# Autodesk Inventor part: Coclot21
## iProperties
Created: 2011-05
Part Number: Coclot21
Document SubType Name: Modeling
Designer: 904Chiaki
Density: 1 g/cm^3
Mass: 303.621 g
Surface Area: 728.501 cm^2
Volume: 303.621 cm^3
Author: 904Chiaki
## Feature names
1. Revolution1
2. Chamfer1
3. Chamfer2
4. Chamfer4
5. Chamfer5
6. Chamfer6
7. Hole1
